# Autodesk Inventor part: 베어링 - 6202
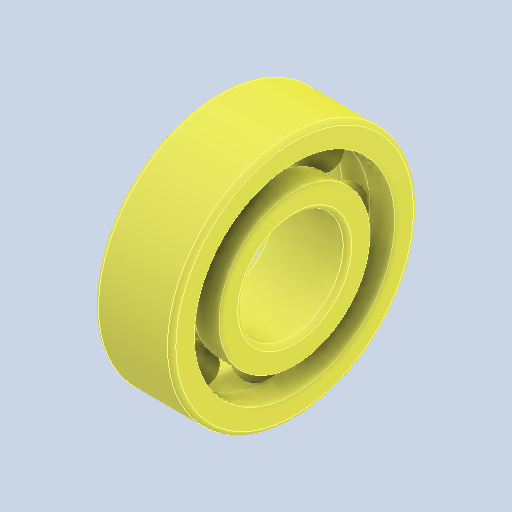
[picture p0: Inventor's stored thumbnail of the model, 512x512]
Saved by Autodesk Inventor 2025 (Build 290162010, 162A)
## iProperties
Created: 2024-07
Part Number: 베어링 - 6202
Material: 강, 연강
Description: 깊은 그루브 볼 베어링
Document SubType Name: Modeling
Designer: Admin
Density: 7.86 g/cm^3
Appearance: 기본값
Author: jhkim
Sending System: Autodesk Inventor 2025
Preprocessor: ST-DEVELOPER v20
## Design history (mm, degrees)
feature "Solid1"
feature "Solid1:1"
feature "Solid1:2"
feature "Solid1:3"
feature "Solid1:4"
feature "Solid1:5"
feature "Solid1:6"
feature "Solid1:7"
feature "Solid1:8"
feature "Solid1:9"
node "솔리드1"
node "솔리드2"
node "솔리드3"
node "솔리드4"
node "솔리드5"
node "솔리드6"
node "솔리드7"
node "솔리드8"
node "솔리드9"
node "솔리드10"
